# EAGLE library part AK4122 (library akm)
Sample Rate Converter with DIR 24-Bit, 96 kHz with Digital Audio Receiver (DIR)
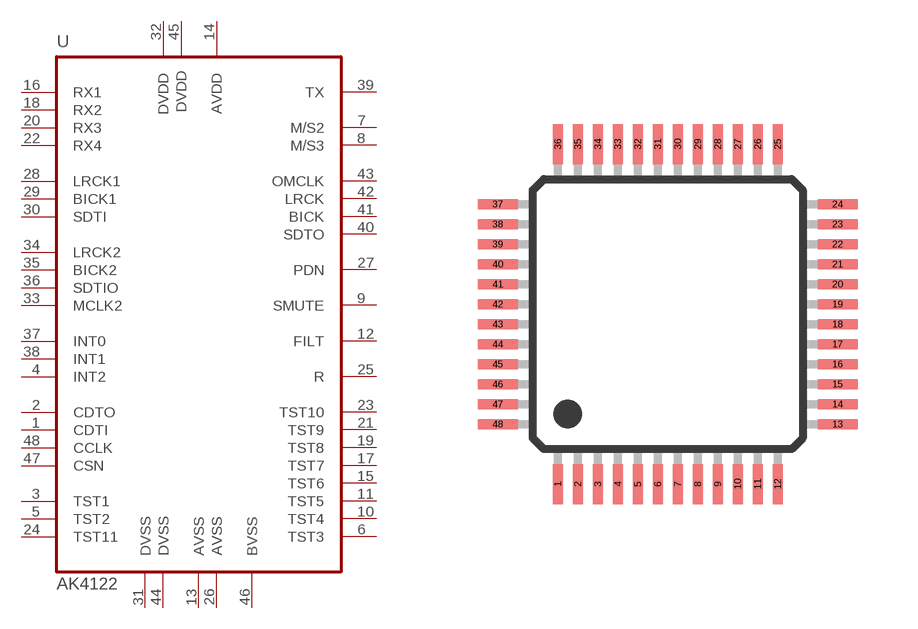
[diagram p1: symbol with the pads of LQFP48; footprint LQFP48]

Designator prefix U

## AK4122VQ  [LQFP48]
1  CDTI  in
2  CDTO  out
3  TST1  nc
4  INT2  out
5  TST2  nc
6  TST3  in
7  M/S2  in
8  M/S3  in
9  SMUTE  in
10  TST4  in
11  TST5  in
12  FILT  out
13  AVSS  pwr
14  AVDD  pwr
15  TST6  in
16  RX1  in
17  TST7  in
18  RX2  in
19  TST8  in
20  RX3  in
21  TST9  in
22  RX4  in
23  TST10  in
24  TST11  nc
25  R  pas
26  AVSS1  pwr
27  PDN  in
28  LRCK1  in
29  BICK1  in
30  SDTI  in
31  DVSS  pwr
32  DVDD  pwr
33  MCLK2  in
34  LRCK2
35  BICK2
36  SDTIO
37  INT0  out
38  INT1  out
39  TX  out
40  SDTO  out
41  BICK
42  LRCK
43  OMCLK  in
44  DVSS1  pwr
45  DVDD1  pwr
46  BVSS  pwr
47  CSN  in
48  CCLK  in

## Footprint LQFP48 (pad centres in mm)
LQFP48
smd 0.25 x 1: 1 -2.75,-4.25; 2 -2.25,-4.25; 3 -1.75,-4.25; 4 -1.25,-4.25; 5 -0.75,-4.25; 6 -0.25,-4.25; 7 0.25,-4.25; 8 0.75,-4.25; 9 1.25,-4.25; 10 1.75,-4.25; 11 2.25,-4.25; 12 2.75,-4.25; 25 2.75,4.25; 26 2.25,4.25; 27 1.75,4.25; 28 1.25,4.25; 29 0.75,4.25; 30 0.25,4.25; 31 -0.25,4.25; 32 -0.75,4.25; 33 -1.25,4.25; 34 -1.75,4.25; 35 -2.25,4.25; 36 -2.75,4.25
smd 1 x 0.25: 13 4.25,-2.75; 14 4.25,-2.25; 15 4.25,-1.75; 16 4.25,-1.25; 17 4.25,-0.75; 18 4.25,-0.25; 19 4.25,0.25; 20 4.25,0.75; 21 4.25,1.25; 22 4.25,1.75; 23 4.25,2.25; 24 4.25,2.75; 37 -4.25,2.75; 38 -4.25,2.25; 39 -4.25,1.75; 40 -4.25,1.25; 41 -4.25,0.75; 42 -4.25,0.25; 43 -4.25,-0.25; 44 -4.25,-0.75; 45 -4.25,-1.25; 46 -4.25,-1.75; 47 -4.25,-2.25; 48 -4.25,-2.75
